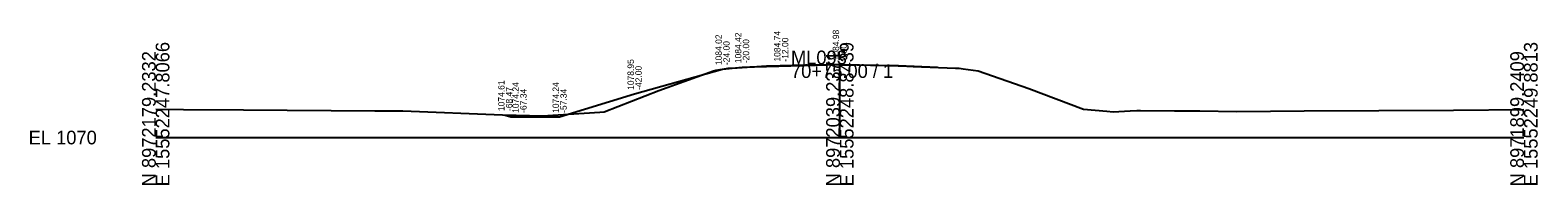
# Model space of a CAD drawing. Extents: x -26 to 14283, y -10 to 28.
# Drawn here: x 10974.3 to 11282.8, y -9.7 to 22 of the extents above; entities that cross this region are included whole.
import ezdxf

# ---------------------------------------------------------------- set-up
doc = ezdxf.new("R2010")
doc.units = 0
for name, color, linetype in [('Default', 7, 'Continuous'), ('dsn3DCenterLine', 7, 'Continuous'), ('dsn3DDitchBack', 7, 'Continuous'), ('dsn3DDitchFront', 7, 'Continuous'), ('dsn3DForeSlopeBarnRoofPoint', 7, 'Continuous'), ('dsn3DForeSlopeBreakLine', 7, 'Continuous'), ('dsn3DGroundLineIntercept', 7, 'Continuous'), ('dsn3DPavementTop', 7, 'Continuous'), ('dsn3DShoulderTop', 7, 'Continuous'), ('dsn3DSubgradeBreakLine', 7, 'Continuous'), ('dsn3DSubgradeHingePoint', 7, 'Continuous'), ('dsnGeopakCellCrossSection', 7, 'Continuous'), ('dsnXSEarthwork', 7, 'Continuous'), ('dsnXsExistingGround', 7, 'Continuous'), ('dsnXsSideSlopes', 7, 'Continuous'), ('dsnXsTextOffsetElevFinGrd', 7, 'Continuous')]:
    doc.layers.add(name, color=color, linetype=linetype)

msp = doc.modelspace()

# ---------------------------------------------------------------- linework, layer by layer
at = {"layer": 'Default'}
msp.add_lwpolyline([(11120, 14.42), (11140, 14.98), (11152, 14.74), (11160, 14.42)], dxfattribs=at)
at = {"layer": 'dsnGeopakCellCrossSection'}
for p, q in [((11140, 0), (11140, 15)), ((11000, 0), (11140, 0)), ((11140, 0), (11280, 0))]:
    msp.add_line(p, q, dxfattribs=at)
at = {"layer": 'dsnXSEarthwork'}
msp.add_lwpolyline([(11120, 14.42), (11128, 14.74), (11140, 14.98), (11152, 14.74), (11160, 14.42)], dxfattribs=at)
at = {"layer": 'dsnXsExistingGround'}
msp.add_lwpolyline([(11000, 5.78), (11005.67, 5.77), (11017.99, 5.68), (11044.87, 5.44), (11050.58, 5.46), (11071, 4.63), (11073.76, 4.55), (11074.73, 4.49), (11076.48, 4.49), (11079.13, 4.46), (11090.87, 5.21), (11091.79, 5.28), (11102.98, 9.65), (11114.12, 13.68), (11114.59, 13.76), (11117.17, 14.22), (11117.77, 14.23), (11117.94, 14.23), (11120.03, 14.34), (11125, 14.66), (11127.81, 14.75), (11138.04, 14.94), (11140, 14.98), (11143.49, 14.89), (11151.94, 14.67), (11153.72, 14.62), (11155, 14.57), (11163.64, 14.2), (11164.41, 14.17), (11165.23, 14.05), (11168.34, 13.65), (11178.65, 10.02), (11189.89, 5.81), (11194.62, 5.39), (11195.94, 5.28), (11199.44, 5.47), (11200.8, 5.54), (11201.55, 5.54), (11208.46, 5.48), (11211.77, 5.46), (11213.7, 5.44), (11221.22, 5.36), (11235.04, 5.49), (11265.56, 5.62), (11280, 5.71)], dxfattribs=at)
at = {"layer": 'dsnXsSideSlopes'}
msp.add_lwpolyline([(11071.53, 4.61), (11072.66, 4.24), (11072.66, 4.24), (11082.66, 4.24), (11082.66, 4.24), (11098, 8.95), (11098, 8.95), (11098, 8.95), (11116, 14.02), (11116, 14.02), (11120, 14.42)], dxfattribs=at)

# ---------------------------------------------------------------- texts
msp.add_text('-', height=0.0001).set_placement((11000, 0))
at = {"layer": 'dsn3DCenterLine'}
msp.add_text('X', height=0.00781, dxfattribs=at).set_placement((11140, 14.97))
at = {"layer": 'dsn3DDitchBack'}
msp.add_text('X', height=0.00781, dxfattribs=at).set_placement((11072.65, 4.23))
at = {"layer": 'dsn3DDitchFront'}
for p in [(11177.8, 9.41), (11082.65, 4.23)]:
    msp.add_text('X', height=0.00781, dxfattribs=at).set_placement(p)
at = {"layer": 'dsn3DForeSlopeBarnRoofPoint'}
for p in [(11177.8, 9.41), (11098, 8.95)]:
    msp.add_text('X', height=0.00781, dxfattribs=at).set_placement(p)
at = {"layer": 'dsn3DForeSlopeBreakLine'}
for p in [(11116, 14.01), (11164, 14.01)]:
    msp.add_text('X', height=0.00781, dxfattribs=at).set_placement(p)
at = {"layer": 'dsn3DGroundLineIntercept'}
for p in [(11180.26, 9.41), (11071.52, 4.61)]:
    msp.add_text('X', height=0.00781, dxfattribs=at).set_placement(p)
at = {"layer": 'dsn3DPavementTop'}
for p in [(11128, 14.73), (11152, 14.73)]:
    msp.add_text('X', height=0.00781, dxfattribs=at).set_placement(p)
at = {"layer": 'dsn3DShoulderTop'}
for p in [(11120, 14.41), (11160, 14.41)]:
    msp.add_text('X', height=0.00781, dxfattribs=at).set_placement(p)
at = {"layer": 'dsn3DSubgradeBreakLine'}
for p in [(11128, 13.23), (11140, 13.47)]:
    msp.add_text('X', height=0.00781, dxfattribs=at).set_placement(p)
at = {"layer": 'dsn3DSubgradeHingePoint'}
for p in [(11111.94, 12.87), (11167.42, 12.87)]:
    msp.add_text('X', height=0.00781, dxfattribs=at).set_placement(p)
at = {"layer": 'dsnGeopakCellCrossSection'}
for s, p in [('E 15552247.8066', (11002.8, -10)), ('E 15552248.8439', (11142.8, -10)), ('E 15552249.8813', (11282.8, -10)), ('N 8972179.2332', (11000, -10)), ('N 8972039.2371', (11140, -10)), ('N 8971899.2409', (11280, -10))]:
    msp.add_text(s, height=2.8, rotation=90, dxfattribs=at).set_placement(p)
for s, p in [('ML093', (11130, 15)), ('70+75.00 / 1', (11130, 12.2)), ('EL 1070', (10974, -1.4))]:
    msp.add_text(s, height=2.8, dxfattribs=at).set_placement(p)
at = {"layer": 'dsnXsTextOffsetElevFinGrd'}
for s, p in [('1084.74', (11127.85, 15.54)), ('1084.74', (11127.85, 15.54)), ('1084.98', (11139.85, 15.78)), ('1084.02', (11115.85, 14.82)), ('1084.02', (11115.85, 14.82)), ('-24.00', (11117.45, 14.82)), ('-24.00', (11117.45, 14.82)), ('1084.42', (11119.85, 15.22)), ('-20.00', (11121.45, 15.22)), ('-12.00', (11129.45, 15.54)), ('-12.00', (11129.45, 15.54)), ('0.00', (11141.45, 15.78)), ('1078.95', (11097.85, 9.75)), ('-42.00', (11099.45, 9.75)), ('1074.61', (11071.38, 5.41)), ('-68.47', (11072.98, 5.41)), ('1074.24', (11074.29, 5.04)), ('-67.34', (11075.89, 5.04)), ('1074.24', (11082.51, 5.04)), ('-57.34', (11084.11, 5.04))]:
    msp.add_text(s, height=1.3, rotation=90, dxfattribs=at).set_placement(p)

doc.saveas('drawing.dxf')
